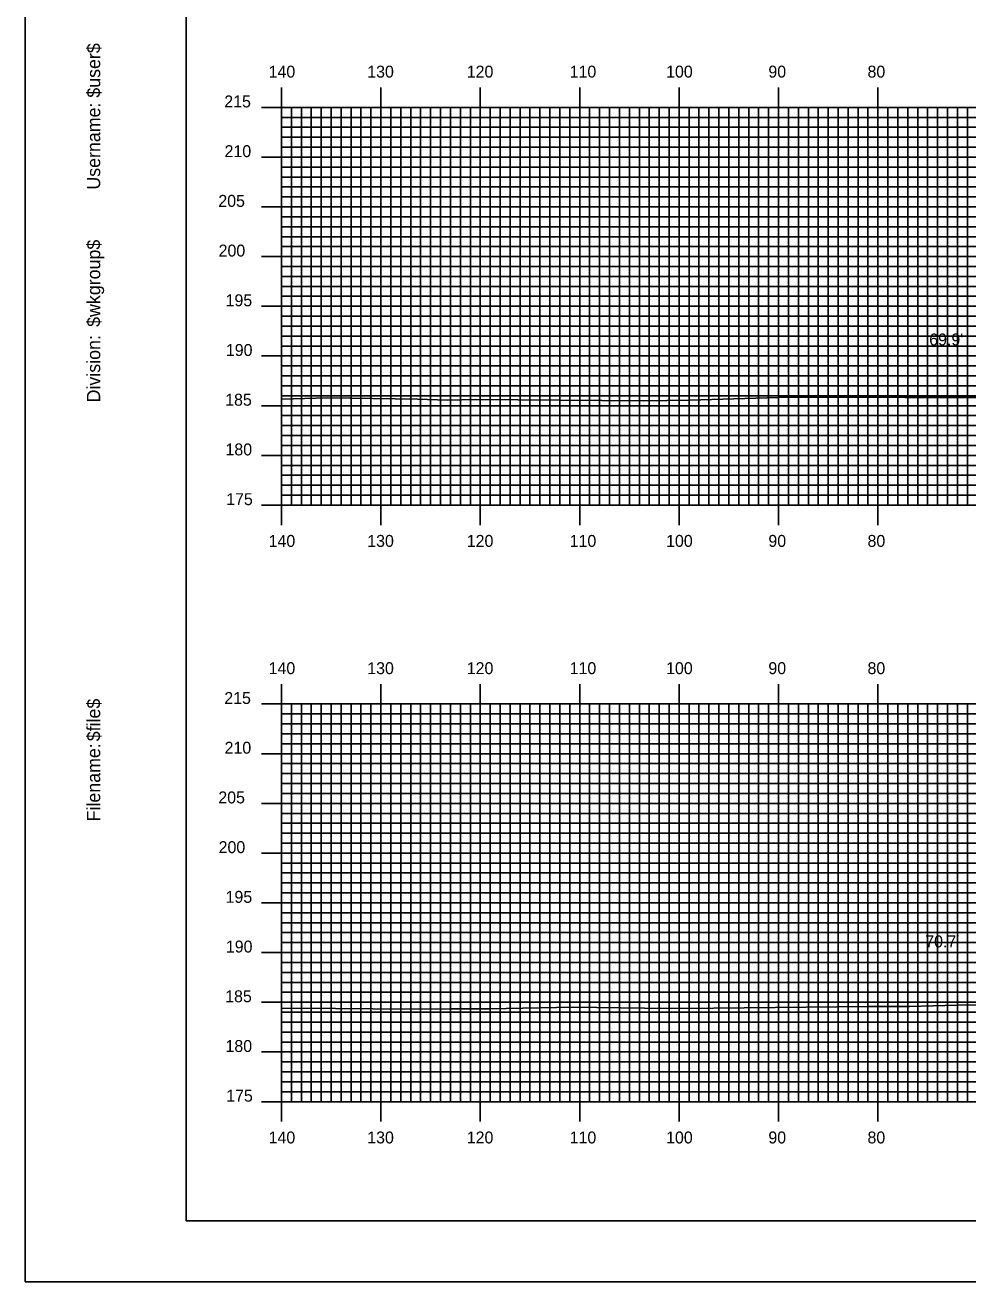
# Model space of a CAD drawing. Extents: x 1810193 to 1810536, y 442591 to 442811.
# Drawn here: x 1810193.1 to 1810287.9, y 442590.5 to 442716.9 of the extents above; entities that cross this region are included whole.
import ezdxf

# ---------------------------------------------------------------- set-up
doc = ezdxf.new("R2010")
doc.units = 0
for name, color, linetype in [('BORDER', 7, 'Continuous'), ('D_Text_Standard', 7, 'Continuous'), ('H_V ANNOTATION', 7, 'Continuous'), ('MAJOR', 7, 'Continuous'), ('MINOR', 7, 'Continuous'), ('PLOT BOUNDARY', 7, 'Continuous'), ('S_Roadway_Centerline', 7, 'Continuous')]:
    doc.layers.add(name, color=color, linetype=linetype)

msp = doc.modelspace()

# ---------------------------------------------------------------- linework, layer by layer
at = {"layer": 'BORDER'}
msp.add_lwpolyline([(1810209.26, 442596.67), (1810529.26, 442596.67), (1810529.26, 442806.67), (1810209.26, 442806.67)], close=True, dxfattribs=at)
at = {"layer": 'MAJOR'}
for p, q in [((1810218.86, 442710.67), (1810218.86, 442708.67)), ((1810228.86, 442710.67), (1810228.86, 442708.67)), ((1810238.86, 442710.67), (1810238.86, 442708.67)), ((1810248.86, 442710.67), (1810248.86, 442708.67)), ((1810258.86, 442710.67), (1810258.86, 442708.67)), ((1810268.86, 442710.67), (1810268.86, 442708.67)), ((1810278.86, 442710.67), (1810278.86, 442708.67)), ((1810216.86, 442708.67), (1810218.86, 442708.67)), ((1810218.86, 442708.67), (1810498.86, 442708.67)), ((1810218.86, 442668.67), (1810218.86, 442708.67)), ((1810218.86, 442668.67), (1810218.86, 442708.67)), ((1810218.86, 442708.67), (1810498.86, 442708.67)), ((1810228.86, 442668.67), (1810228.86, 442708.67)), ((1810238.86, 442668.67), (1810238.86, 442708.67)), ((1810248.86, 442668.67), (1810248.86, 442708.67)), ((1810258.86, 442668.67), (1810258.86, 442708.67)), ((1810268.86, 442668.67), (1810268.86, 442708.67)), ((1810278.86, 442668.67), (1810278.86, 442708.67)), ((1810216.86, 442703.67), (1810218.86, 442703.67)), ((1810218.86, 442703.67), (1810498.86, 442703.67)), ((1810216.86, 442698.67), (1810218.86, 442698.67)), ((1810218.86, 442698.67), (1810498.86, 442698.67)), ((1810216.86, 442693.67), (1810218.86, 442693.67)), ((1810218.86, 442693.67), (1810498.86, 442693.67)), ((1810216.86, 442688.67), (1810218.86, 442688.67)), ((1810218.86, 442688.67), (1810498.86, 442688.67)), ((1810216.86, 442683.67), (1810218.86, 442683.67)), ((1810218.86, 442683.67), (1810498.86, 442683.67)), ((1810216.86, 442678.67), (1810218.86, 442678.67)), ((1810218.86, 442678.67), (1810498.86, 442678.67)), ((1810216.86, 442673.67), (1810218.86, 442673.67)), ((1810218.86, 442673.67), (1810498.86, 442673.67)), ((1810216.86, 442668.67), (1810218.86, 442668.67)), ((1810218.86, 442668.67), (1810498.86, 442668.67)), ((1810218.86, 442668.67), (1810498.86, 442668.67)), ((1810218.86, 442666.66), (1810218.86, 442668.67)), ((1810228.86, 442666.66), (1810228.86, 442668.67)), ((1810238.86, 442666.66), (1810238.86, 442668.67)), ((1810248.86, 442666.66), (1810248.86, 442668.67)), ((1810258.86, 442666.66), (1810258.86, 442668.67)), ((1810268.86, 442666.66), (1810268.86, 442668.67)), ((1810278.86, 442666.66), (1810278.86, 442668.67)), ((1810218.86, 442650.67), (1810218.86, 442648.67)), ((1810228.86, 442650.67), (1810228.86, 442648.67)), ((1810238.86, 442650.67), (1810238.86, 442648.67)), ((1810248.86, 442650.67), (1810248.86, 442648.67)), ((1810258.86, 442650.67), (1810258.86, 442648.67)), ((1810268.86, 442650.67), (1810268.86, 442648.67)), ((1810278.86, 442650.67), (1810278.86, 442648.67)), ((1810216.86, 442648.67), (1810218.86, 442648.67)), ((1810218.86, 442648.67), (1810498.86, 442648.67)), ((1810218.86, 442608.67), (1810218.86, 442648.67)), ((1810218.86, 442608.67), (1810218.86, 442648.67)), ((1810218.86, 442648.67), (1810498.86, 442648.67)), ((1810228.86, 442608.67), (1810228.86, 442648.67)), ((1810238.86, 442608.67), (1810238.86, 442648.67)), ((1810248.86, 442608.67), (1810248.86, 442648.67)), ((1810258.86, 442608.67), (1810258.86, 442648.67)), ((1810268.86, 442608.67), (1810268.86, 442648.67)), ((1810278.86, 442608.67), (1810278.86, 442648.67)), ((1810216.86, 442643.67), (1810218.86, 442643.67)), ((1810218.86, 442643.67), (1810498.86, 442643.67)), ((1810216.86, 442638.67), (1810218.86, 442638.67)), ((1810218.86, 442638.67), (1810498.86, 442638.67)), ((1810216.86, 442633.67), (1810218.86, 442633.67)), ((1810218.86, 442633.67), (1810498.86, 442633.67)), ((1810216.86, 442628.67), (1810218.86, 442628.67)), ((1810218.86, 442628.67), (1810498.86, 442628.67)), ((1810216.86, 442623.67), (1810218.86, 442623.67)), ((1810218.86, 442623.67), (1810498.86, 442623.67)), ((1810216.86, 442618.67), (1810218.86, 442618.67)), ((1810218.86, 442618.67), (1810498.86, 442618.67)), ((1810216.86, 442613.67), (1810218.86, 442613.67)), ((1810218.86, 442613.67), (1810498.86, 442613.67)), ((1810216.86, 442608.67), (1810218.86, 442608.67)), ((1810218.86, 442608.67), (1810498.86, 442608.67)), ((1810218.86, 442608.67), (1810498.86, 442608.67)), ((1810218.86, 442606.66), (1810218.86, 442608.67)), ((1810228.86, 442606.66), (1810228.86, 442608.67)), ((1810238.86, 442606.66), (1810238.86, 442608.67)), ((1810248.86, 442606.66), (1810248.86, 442608.67)), ((1810258.86, 442606.66), (1810258.86, 442608.67)), ((1810268.86, 442606.66), (1810268.86, 442608.67)), ((1810278.86, 442606.66), (1810278.86, 442608.67))]:
    msp.add_line(p, q, dxfattribs=at)
at = {"layer": 'MINOR'}
for p, q in [((1810219.86, 442668.67), (1810219.86, 442708.67)), ((1810220.86, 442668.67), (1810220.86, 442708.67)), ((1810221.86, 442668.67), (1810221.86, 442708.67)), ((1810222.86, 442668.67), (1810222.86, 442708.67)), ((1810223.86, 442668.67), (1810223.86, 442708.67)), ((1810224.86, 442668.67), (1810224.86, 442708.67)), ((1810225.86, 442668.67), (1810225.86, 442708.67)), ((1810226.86, 442668.67), (1810226.86, 442708.67)), ((1810227.86, 442668.67), (1810227.86, 442708.67)), ((1810229.86, 442668.67), (1810229.86, 442708.67)), ((1810230.86, 442668.67), (1810230.86, 442708.67)), ((1810231.86, 442668.67), (1810231.86, 442708.67)), ((1810232.86, 442668.67), (1810232.86, 442708.67)), ((1810233.86, 442668.67), (1810233.86, 442708.67)), ((1810234.86, 442668.67), (1810234.86, 442708.67)), ((1810235.86, 442668.67), (1810235.86, 442708.67)), ((1810236.86, 442668.67), (1810236.86, 442708.67)), ((1810237.86, 442668.67), (1810237.86, 442708.67)), ((1810239.86, 442668.67), (1810239.86, 442708.67)), ((1810240.86, 442668.67), (1810240.86, 442708.67)), ((1810241.86, 442668.67), (1810241.86, 442708.67)), ((1810242.86, 442668.67), (1810242.86, 442708.67)), ((1810243.86, 442668.67), (1810243.86, 442708.67)), ((1810244.86, 442668.67), (1810244.86, 442708.67)), ((1810245.86, 442668.67), (1810245.86, 442708.67)), ((1810246.86, 442668.67), (1810246.86, 442708.67)), ((1810247.86, 442668.67), (1810247.86, 442708.67)), ((1810249.86, 442668.67), (1810249.86, 442708.67)), ((1810250.86, 442668.67), (1810250.86, 442708.67)), ((1810251.86, 442668.67), (1810251.86, 442708.67)), ((1810252.86, 442668.67), (1810252.86, 442708.67)), ((1810253.86, 442668.67), (1810253.86, 442708.67)), ((1810254.86, 442668.67), (1810254.86, 442708.67)), ((1810255.86, 442668.67), (1810255.86, 442708.67)), ((1810256.86, 442668.67), (1810256.86, 442708.67)), ((1810257.86, 442668.67), (1810257.86, 442708.67)), ((1810259.86, 442668.67), (1810259.86, 442708.67)), ((1810260.86, 442668.67), (1810260.86, 442708.67)), ((1810261.86, 442668.67), (1810261.86, 442708.67)), ((1810262.86, 442668.67), (1810262.86, 442708.67)), ((1810263.86, 442668.67), (1810263.86, 442708.67)), ((1810264.86, 442668.67), (1810264.86, 442708.67)), ((1810265.86, 442668.67), (1810265.86, 442708.67)), ((1810266.86, 442668.67), (1810266.86, 442708.67)), ((1810267.86, 442668.67), (1810267.86, 442708.67)), ((1810269.86, 442668.67), (1810269.86, 442708.67)), ((1810270.86, 442668.67), (1810270.86, 442708.67)), ((1810271.86, 442668.67), (1810271.86, 442708.67)), ((1810272.86, 442668.67), (1810272.86, 442708.67)), ((1810273.86, 442668.67), (1810273.86, 442708.67)), ((1810274.86, 442668.67), (1810274.86, 442708.67)), ((1810275.86, 442668.67), (1810275.86, 442708.67)), ((1810276.86, 442668.67), (1810276.86, 442708.67)), ((1810277.86, 442668.67), (1810277.86, 442708.67)), ((1810279.86, 442668.67), (1810279.86, 442708.67)), ((1810280.86, 442668.67), (1810280.86, 442708.67)), ((1810281.86, 442668.67), (1810281.86, 442708.67)), ((1810282.86, 442668.67), (1810282.86, 442708.67)), ((1810283.86, 442668.67), (1810283.86, 442708.67)), ((1810284.86, 442668.67), (1810284.86, 442708.67)), ((1810285.86, 442668.67), (1810285.86, 442708.67)), ((1810286.86, 442668.67), (1810286.86, 442708.67)), ((1810287.86, 442668.67), (1810287.86, 442708.67)), ((1810218.86, 442707.67), (1810498.86, 442707.67)), ((1810218.86, 442707.67), (1810220.87, 442707.67)), ((1810218.86, 442706.67), (1810498.86, 442706.67)), ((1810218.86, 442706.67), (1810220.87, 442706.67)), ((1810218.86, 442705.67), (1810498.86, 442705.67)), ((1810218.86, 442705.67), (1810220.87, 442705.67)), ((1810218.86, 442704.67), (1810498.86, 442704.67)), ((1810218.86, 442704.67), (1810220.87, 442704.67)), ((1810218.86, 442702.67), (1810498.86, 442702.67)), ((1810218.86, 442702.67), (1810220.87, 442702.67)), ((1810218.86, 442701.67), (1810498.86, 442701.67)), ((1810218.86, 442701.67), (1810220.87, 442701.67)), ((1810218.86, 442700.67), (1810498.86, 442700.67)), ((1810218.86, 442700.67), (1810220.87, 442700.67)), ((1810218.86, 442699.67), (1810498.86, 442699.67)), ((1810218.86, 442699.67), (1810220.87, 442699.67)), ((1810218.86, 442697.67), (1810498.86, 442697.67)), ((1810218.86, 442697.67), (1810220.87, 442697.67)), ((1810218.86, 442696.67), (1810498.86, 442696.67)), ((1810218.86, 442696.67), (1810220.87, 442696.67)), ((1810218.86, 442695.67), (1810498.86, 442695.67)), ((1810218.86, 442695.67), (1810220.87, 442695.67)), ((1810218.86, 442694.67), (1810498.86, 442694.67)), ((1810218.86, 442694.67), (1810220.87, 442694.67)), ((1810218.86, 442692.67), (1810498.86, 442692.67)), ((1810218.86, 442692.67), (1810220.87, 442692.67)), ((1810218.86, 442691.67), (1810498.86, 442691.67)), ((1810218.86, 442691.67), (1810220.87, 442691.67)), ((1810218.86, 442690.67), (1810498.86, 442690.67)), ((1810218.86, 442690.67), (1810220.87, 442690.67)), ((1810218.86, 442689.67), (1810498.86, 442689.67)), ((1810218.86, 442689.67), (1810220.87, 442689.67)), ((1810218.86, 442687.67), (1810498.86, 442687.67)), ((1810218.86, 442687.67), (1810220.87, 442687.67)), ((1810218.86, 442686.67), (1810498.86, 442686.67)), ((1810218.86, 442686.67), (1810220.87, 442686.67)), ((1810218.86, 442685.67), (1810498.86, 442685.67)), ((1810218.86, 442685.67), (1810220.87, 442685.67)), ((1810218.86, 442684.67), (1810498.86, 442684.67)), ((1810218.86, 442684.67), (1810220.87, 442684.67)), ((1810218.86, 442682.67), (1810498.86, 442682.67)), ((1810218.86, 442682.67), (1810220.87, 442682.67)), ((1810218.86, 442681.67), (1810498.86, 442681.67)), ((1810218.86, 442681.67), (1810220.87, 442681.67)), ((1810218.86, 442680.67), (1810498.86, 442680.67)), ((1810218.86, 442680.67), (1810220.87, 442680.67)), ((1810218.86, 442679.67), (1810498.86, 442679.67)), ((1810218.86, 442679.67), (1810220.87, 442679.67)), ((1810218.86, 442677.67), (1810498.86, 442677.67)), ((1810218.86, 442677.67), (1810220.87, 442677.67)), ((1810218.86, 442676.67), (1810498.86, 442676.67)), ((1810218.86, 442676.67), (1810220.87, 442676.67)), ((1810218.86, 442675.67), (1810498.86, 442675.67)), ((1810218.86, 442675.67), (1810220.87, 442675.67)), ((1810218.86, 442674.67), (1810498.86, 442674.67)), ((1810218.86, 442674.67), (1810220.87, 442674.67)), ((1810218.86, 442672.67), (1810498.86, 442672.67)), ((1810218.86, 442672.67), (1810220.87, 442672.67)), ((1810218.86, 442671.67), (1810498.86, 442671.67)), ((1810218.86, 442671.67), (1810220.87, 442671.67)), ((1810218.86, 442670.67), (1810498.86, 442670.67)), ((1810218.86, 442670.67), (1810220.87, 442670.67)), ((1810218.86, 442669.67), (1810498.86, 442669.67)), ((1810218.86, 442669.67), (1810220.87, 442669.67)), ((1810219.86, 442608.67), (1810219.86, 442648.67)), ((1810220.86, 442608.67), (1810220.86, 442648.67)), ((1810221.86, 442608.67), (1810221.86, 442648.67)), ((1810222.86, 442608.67), (1810222.86, 442648.67)), ((1810223.86, 442608.67), (1810223.86, 442648.67)), ((1810224.86, 442608.67), (1810224.86, 442648.67)), ((1810225.86, 442608.67), (1810225.86, 442648.67)), ((1810226.86, 442608.67), (1810226.86, 442648.67)), ((1810227.86, 442608.67), (1810227.86, 442648.67)), ((1810229.86, 442608.67), (1810229.86, 442648.67)), ((1810230.86, 442608.67), (1810230.86, 442648.67)), ((1810231.86, 442608.67), (1810231.86, 442648.67)), ((1810232.86, 442608.67), (1810232.86, 442648.67)), ((1810233.86, 442608.67), (1810233.86, 442648.67)), ((1810234.86, 442608.67), (1810234.86, 442648.67)), ((1810235.86, 442608.67), (1810235.86, 442648.67)), ((1810236.86, 442608.67), (1810236.86, 442648.67)), ((1810237.86, 442608.67), (1810237.86, 442648.67)), ((1810239.86, 442608.67), (1810239.86, 442648.67)), ((1810240.86, 442608.67), (1810240.86, 442648.67)), ((1810241.86, 442608.67), (1810241.86, 442648.67)), ((1810242.86, 442608.67), (1810242.86, 442648.67)), ((1810243.86, 442608.67), (1810243.86, 442648.67)), ((1810244.86, 442608.67), (1810244.86, 442648.67)), ((1810245.86, 442608.67), (1810245.86, 442648.67)), ((1810246.86, 442608.67), (1810246.86, 442648.67)), ((1810247.86, 442608.67), (1810247.86, 442648.67)), ((1810249.86, 442608.67), (1810249.86, 442648.67)), ((1810250.86, 442608.67), (1810250.86, 442648.67)), ((1810251.86, 442608.67), (1810251.86, 442648.67)), ((1810252.86, 442608.67), (1810252.86, 442648.67)), ((1810253.86, 442608.67), (1810253.86, 442648.67)), ((1810254.86, 442608.67), (1810254.86, 442648.67)), ((1810255.86, 442608.67), (1810255.86, 442648.67)), ((1810256.86, 442608.67), (1810256.86, 442648.67)), ((1810257.86, 442608.67), (1810257.86, 442648.67)), ((1810259.86, 442608.67), (1810259.86, 442648.67)), ((1810260.86, 442608.67), (1810260.86, 442648.67)), ((1810261.86, 442608.67), (1810261.86, 442648.67)), ((1810262.86, 442608.67), (1810262.86, 442648.67)), ((1810263.86, 442608.67), (1810263.86, 442648.67)), ((1810264.86, 442608.67), (1810264.86, 442648.67)), ((1810265.86, 442608.67), (1810265.86, 442648.67)), ((1810266.86, 442608.67), (1810266.86, 442648.67)), ((1810267.86, 442608.67), (1810267.86, 442648.67)), ((1810269.86, 442608.67), (1810269.86, 442648.67)), ((1810270.86, 442608.67), (1810270.86, 442648.67)), ((1810271.86, 442608.67), (1810271.86, 442648.67)), ((1810272.86, 442608.67), (1810272.86, 442648.67)), ((1810273.86, 442608.67), (1810273.86, 442648.67)), ((1810274.86, 442608.67), (1810274.86, 442648.67)), ((1810275.86, 442608.67), (1810275.86, 442648.67)), ((1810276.86, 442608.67), (1810276.86, 442648.67)), ((1810277.86, 442608.67), (1810277.86, 442648.67)), ((1810279.86, 442608.67), (1810279.86, 442648.67)), ((1810280.86, 442608.67), (1810280.86, 442648.67)), ((1810281.86, 442608.67), (1810281.86, 442648.67)), ((1810282.86, 442608.67), (1810282.86, 442648.67)), ((1810283.86, 442608.67), (1810283.86, 442648.67)), ((1810284.86, 442608.67), (1810284.86, 442648.67)), ((1810285.86, 442608.67), (1810285.86, 442648.67)), ((1810286.86, 442608.67), (1810286.86, 442648.67)), ((1810287.86, 442608.67), (1810287.86, 442648.67)), ((1810218.86, 442647.67), (1810498.86, 442647.67)), ((1810218.86, 442647.67), (1810220.87, 442647.67)), ((1810218.86, 442646.67), (1810498.86, 442646.67)), ((1810218.86, 442646.67), (1810220.87, 442646.67)), ((1810218.86, 442645.67), (1810498.86, 442645.67)), ((1810218.86, 442645.67), (1810220.87, 442645.67)), ((1810218.86, 442644.67), (1810498.86, 442644.67)), ((1810218.86, 442644.67), (1810220.87, 442644.67)), ((1810218.86, 442642.67), (1810498.86, 442642.67)), ((1810218.86, 442642.67), (1810220.87, 442642.67)), ((1810218.86, 442641.67), (1810498.86, 442641.67)), ((1810218.86, 442641.67), (1810220.87, 442641.67)), ((1810218.86, 442640.67), (1810498.86, 442640.67)), ((1810218.86, 442640.67), (1810220.87, 442640.67)), ((1810218.86, 442639.67), (1810498.86, 442639.67)), ((1810218.86, 442639.67), (1810220.87, 442639.67)), ((1810218.86, 442637.67), (1810498.86, 442637.67)), ((1810218.86, 442637.67), (1810220.87, 442637.67)), ((1810218.86, 442636.67), (1810498.86, 442636.67)), ((1810218.86, 442636.67), (1810220.87, 442636.67)), ((1810218.86, 442635.67), (1810498.86, 442635.67)), ((1810218.86, 442635.67), (1810220.87, 442635.67)), ((1810218.86, 442634.67), (1810498.86, 442634.67)), ((1810218.86, 442634.67), (1810220.87, 442634.67)), ((1810218.86, 442632.67), (1810498.86, 442632.67)), ((1810218.86, 442632.67), (1810220.87, 442632.67)), ((1810218.86, 442631.67), (1810498.86, 442631.67)), ((1810218.86, 442631.67), (1810220.87, 442631.67)), ((1810218.86, 442630.67), (1810498.86, 442630.67)), ((1810218.86, 442630.67), (1810220.87, 442630.67)), ((1810218.86, 442629.67), (1810498.86, 442629.67)), ((1810218.86, 442629.67), (1810220.87, 442629.67)), ((1810218.86, 442627.67), (1810498.86, 442627.67)), ((1810218.86, 442627.67), (1810220.87, 442627.67)), ((1810218.86, 442626.67), (1810498.86, 442626.67)), ((1810218.86, 442626.67), (1810220.87, 442626.67)), ((1810218.86, 442625.67), (1810498.86, 442625.67)), ((1810218.86, 442625.67), (1810220.87, 442625.67)), ((1810218.86, 442624.67), (1810498.86, 442624.67)), ((1810218.86, 442624.67), (1810220.87, 442624.67)), ((1810218.86, 442622.67), (1810498.86, 442622.67)), ((1810218.86, 442622.67), (1810220.87, 442622.67)), ((1810218.86, 442621.67), (1810498.86, 442621.67)), ((1810218.86, 442621.67), (1810220.87, 442621.67)), ((1810218.86, 442620.67), (1810498.86, 442620.67)), ((1810218.86, 442620.67), (1810220.87, 442620.67)), ((1810218.86, 442619.67), (1810498.86, 442619.67)), ((1810218.86, 442619.67), (1810220.87, 442619.67)), ((1810218.86, 442617.67), (1810498.86, 442617.67)), ((1810218.86, 442617.67), (1810220.87, 442617.67)), ((1810218.86, 442616.67), (1810498.86, 442616.67)), ((1810218.86, 442616.67), (1810220.87, 442616.67)), ((1810218.86, 442615.67), (1810498.86, 442615.67)), ((1810218.86, 442615.67), (1810220.87, 442615.67)), ((1810218.86, 442614.67), (1810498.86, 442614.67)), ((1810218.86, 442614.67), (1810220.87, 442614.67)), ((1810218.86, 442612.67), (1810498.86, 442612.67)), ((1810218.86, 442612.67), (1810220.87, 442612.67)), ((1810218.86, 442611.67), (1810498.86, 442611.67)), ((1810218.86, 442611.67), (1810220.87, 442611.67)), ((1810218.86, 442610.67), (1810498.86, 442610.67)), ((1810218.86, 442610.67), (1810220.87, 442610.67)), ((1810218.86, 442609.67), (1810498.86, 442609.67)), ((1810218.86, 442609.67), (1810220.87, 442609.67))]:
    msp.add_line(p, q, dxfattribs=at)
at = {"layer": 'PLOT BOUNDARY'}
msp.add_lwpolyline([(1810193.08, 442590.55), (1810533.08, 442590.55), (1810533.08, 442810.55), (1810193.08, 442810.55)], close=True, dxfattribs=at)
at = {"layer": 'S_Roadway_Centerline'}
for points in [[(1810218.86, 442679.33), (1810223.52, 442679.46), (1810232.55, 442679.31), (1810235.55, 442679.24), (1810238.4, 442679.29), (1810255.31, 442679.17), (1810259.95, 442679.22), (1810269.89, 442679.53), (1810279.08, 442679.53), (1810281.57, 442679.51), (1810292.74, 442679.5), (1810302.79, 442680.16), (1810303.87, 442680.2), (1810304.85, 442680.19), (1810327.96, 442679.07), (1810328.94, 442679.08), (1810335.58, 442679.14), (1810348.84, 442679.4), (1810353.3, 442679.27), (1810362.8, 442679.18), (1810373.06, 442679.41), (1810374.7, 442679.44), (1810376.62, 442679.44), (1810394.66, 442679.11)], [(1810218.86, 442618.09), (1810224.29, 442618.04), (1810231.81, 442617.98), (1810235.98, 442618.02), (1810239.79, 442618.02), (1810248.19, 442618.17), (1810255.37, 442618.07), (1810259.19, 442618.04), (1810277.83, 442618.24), (1810282.03, 442618.25), (1810286.79, 442618.37), (1810294.97, 442618.44), (1810301.27, 442618.44), (1810310.91, 442618.2), (1810317.65, 442618.08), (1810323.64, 442618.14), (1810333.53, 442618.22), (1810347.79, 442618.47), (1810356.88, 442618.53), (1810362.8, 442618.28), (1810369.05, 442618.33), (1810380.51, 442618.21), (1810392.97, 442618.12)]]:
    msp.add_lwpolyline(points, dxfattribs=at)

# ---------------------------------------------------------------- texts
at = {"layer": 'BORDER'}
for s, p in [('$user$', (1810200.63, 442709.65)), ('Username:', (1810200.63, 442700.4)), ('$wkgroup$', (1810200.63, 442686.6)), ('Division:', (1810200.63, 442679)), ('$file$', (1810200.63, 442644.92)), ('Filename:', (1810200.63, 442636.86))]:
    msp.add_text(s, height=1.339, rotation=90, dxfattribs=at).set_placement(p)
at = {"layer": 'D_Text_Standard'}
for s, p in [("69.9'", (1810284.02, 442684.73)), ("70.7'", (1810283.62, 442624.19))]:
    msp.add_text(s, height=1.2, dxfattribs=at).set_placement(p)
at = {"layer": 'H_V ANNOTATION'}
for s, p in [('140', (1810217.57, 442711.67)), ('130', (1810227.49, 442711.67)), ('120', (1810237.5, 442711.67)), ('110', (1810247.85, 442711.67)), ('100', (1810257.55, 442711.67)), ('90', (1810267.84, 442711.67)), ('80', (1810277.81, 442711.67)), ('215', (1810213.11, 442708.67)), ('210', (1810213.14, 442703.67)), ('205', (1810212.51, 442698.67)), ('200', (1810212.54, 442693.67)), ('195', (1810213.24, 442688.67)), ('190', (1810213.27, 442683.67)), ('185', (1810213.2, 442678.67)), ('180', (1810213.23, 442673.67)), ('175', (1810213.3, 442668.67)), ('140', (1810217.57, 442664.47)), ('130', (1810227.49, 442664.47)), ('120', (1810237.5, 442664.47)), ('110', (1810247.85, 442664.47)), ('100', (1810257.55, 442664.47)), ('90', (1810267.84, 442664.47)), ('80', (1810277.81, 442664.47)), ('140', (1810217.57, 442651.67)), ('130', (1810227.49, 442651.67)), ('120', (1810237.5, 442651.67)), ('110', (1810247.85, 442651.67)), ('100', (1810257.55, 442651.67)), ('90', (1810267.84, 442651.67)), ('80', (1810277.81, 442651.67)), ('215', (1810213.11, 442648.67)), ('210', (1810213.14, 442643.67)), ('205', (1810212.51, 442638.67)), ('200', (1810212.54, 442633.67)), ('195', (1810213.24, 442628.67)), ('190', (1810213.27, 442623.67)), ('185', (1810213.2, 442618.67)), ('180', (1810213.23, 442613.67)), ('175', (1810213.3, 442608.67)), ('140', (1810217.57, 442604.47)), ('130', (1810227.49, 442604.47)), ('120', (1810237.5, 442604.47)), ('110', (1810247.85, 442604.47)), ('100', (1810257.55, 442604.47)), ('90', (1810267.84, 442604.47)), ('80', (1810277.81, 442604.47))]:
    msp.add_text(s, height=1.2, dxfattribs=at).set_placement(p)
at = {"layer": 'MAJOR'}
for p in [(1810218.85, 442668.67), (1810218.85, 442608.67)]:
    msp.add_text('-', height=0.012, dxfattribs=at).set_placement(p)

doc.saveas('drawing.dxf')
